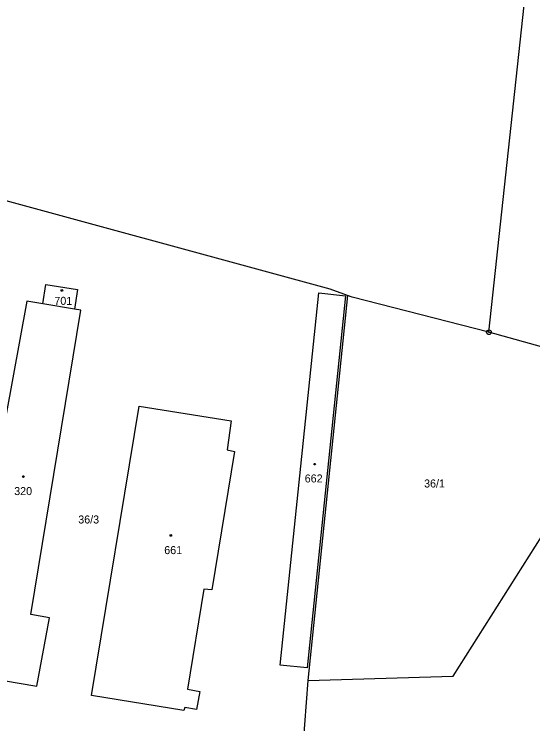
# Model space of a CAD drawing. Extents: x -783948 to -781889, y -1005870 to -1004430.
# Drawn here: x -782523.7 to -782413.6, y -1005661.9 to -1005511.3 of the extents above; entities that cross this region are included whole.
import ezdxf

# ---------------------------------------------------------------- set-up
doc = ezdxf.new("R2010")
doc.units = 0
for name, color, linetype in [('Vrstva 1', 7, 'Continuous'), ('Vrstva 2', 7, 'Continuous'), ('Vrstva 5', 7, 'Continuous'), ('Vrstva 8', 7, 'Continuous')]:
    doc.layers.add(name, color=color, linetype=linetype)

msp = doc.modelspace()

# ---------------------------------------------------------------- linework, layer by layer
at = {"layer": 'Vrstva 1'}
for p, q in [((-782517.64, -1005572.78), (-782517.01, -1005568.73)), ((-782517.01, -1005568.73), (-782510.29, -1005569.77)), ((-782510.29, -1005569.77), (-782510.94, -1005573.92)), ((-782452.94, -1005571.06), (-782461.42, -1005652.75)), ((-782510.94, -1005573.92), (-782517.64, -1005572.78)), ((-782393.59, -1005587.03), (-782422.93, -1005578.83))]:
    msp.add_line(p, q, dxfattribs=at)
for points in [[(-782422.93, -1005578.83), (-782409.11, -1005450.42), (-782367.1, -1005452.62)], [(-782452.94, -1005571.06), (-782456.68, -1005569.69), (-782536.45, -1005547.96)], [(-782459.05, -1005570.48), (-782453.42, -1005571.1), (-782461.52, -1005650.07), (-782467.29, -1005649.47), (-782459.05, -1005570.48)], [(-782422.93, -1005578.83), (-782451.97, -1005571.42), (-782452.94, -1005571.06)], [(-782517.64, -1005572.78), (-782521.05, -1005572.25), (-782532.9, -1005636.58), (-782536.7, -1005635.93), (-782539.38, -1005650.47), (-782518.91, -1005653.99), (-782516.23, -1005639.45), (-782520.22, -1005638.76), (-782509.61, -1005574.13), (-782510.94, -1005573.92)], [(-782461.42, -1005652.75), (-782430.52, -1005651.81), (-782411.71, -1005622.13), (-782407.58, -1005613.07), (-782403.07, -1005592.19), (-782400.3, -1005589.18), (-782393.59, -1005587.03)], [(-782477.64, -1005597.67), (-782478.53, -1005603.79), (-782476.94, -1005604.14), (-782481.8, -1005633.52), (-782483.46, -1005633.35), (-782486.91, -1005654.6), (-782484.34, -1005655.12), (-782485.02, -1005658.91), (-782487.51, -1005658.52), (-782487.71, -1005659.16), (-782507.35, -1005655.92), (-782497.21, -1005594.51), (-782477.64, -1005597.67)], [(-782461.42, -1005652.75), (-782463.16, -1005676.14), (-782468.7, -1005710.19)]]:
    msp.add_lwpolyline(points, dxfattribs=at)
at = {"layer": 'Vrstva 5'}
for centre in [(-782513.62, -1005569.96), (-782459.93, -1005606.84), (-782521.8, -1005609.47), (-782490.48, -1005621.97)]:
    msp.add_circle(centre, 0.175, dxfattribs=at)
at = {"layer": 'Vrstva 8'}
for radius in [0.5, 0.0303]:
    msp.add_circle((-782422.93, -1005578.83), radius, dxfattribs=at)

# ---------------------------------------------------------------- texts
at = {"layer": 'Vrstva 2'}
for s, p in [('701', (-782515.21, -1005573.02)), ('662', (-782462.05, -1005610.72)), ('36/1', (-782436.7, -1005611.79)), ('320', (-782523.74, -1005613.4)), ('36/3', (-782510.14, -1005619.43)), ('661', (-782491.88, -1005625.93))]:
    msp.add_text(s, height=1.7, dxfattribs=at).set_placement(p)

doc.saveas('drawing.dxf')
